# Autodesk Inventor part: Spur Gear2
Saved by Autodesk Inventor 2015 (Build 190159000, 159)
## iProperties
Created: 2014-06
Part Number: Spur Gear2
Material: Steel
Document SubType Name: Modeling
Designer: User
Categories: <?xml version="1.0" encoding="UTF-16"?> <MemberInstance><Categories><FamilyTemplate><FamilyTemplateParameter ValueType="xs:double" Id="1" ObjectReferenceKey="da
Density: 1 g/cm^3
Appearance: Steel
CustomPartVersion: 1
Author: User
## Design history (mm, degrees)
sketch "Sketch1"
  geometry: C1 r 7.579 at (0, 0)
  constraints: 1 centre point
  dimensions: "d0" = 15.1583 diameter of C1 (= da_da)
extrude "Extrusion1" new body sketch "Sketch1" distance "d1" = 6 (= da_b); taper "d2" = 0 deg
workplane "Work Plane2"
sketch "Sketch2"
  geometry: C1 r 7.579 at (0, 0) reference; C2 r 7 at (0, 0)
  constraints: 1 centre point, 1 coincident
  dimensions: "d3" = 14 diameter of C2 (= da_dw)
feature "Pitch Diameter" sketch "Sketch2" dims "d4" = 10, "d5" = 0
workplane "Work Plane8"
workplane "Work Plane9"
feature "Spur Gear" dims "da_b" = 6, "da_d" = 13.92, "da_aw" = 14, "da_da" = 15.1583, "da_df" = 12.5517, "da_dw" = 14, angle "da_beta" = 0 deg, "da_lefttooth" = 0, "da_righttooth" = 0
body "Solid1"
body "Srf1"
other parameters: "d16" = 14 (= da_aw), "d17" = 0, "d34" = 7.5 deg (computed from da_z), "d39" = 0, "d41" = 0, "d43" = 14 (= da_aw), "d46" = 14 (= da_aw), "d47" = 0, "d48" = 0
